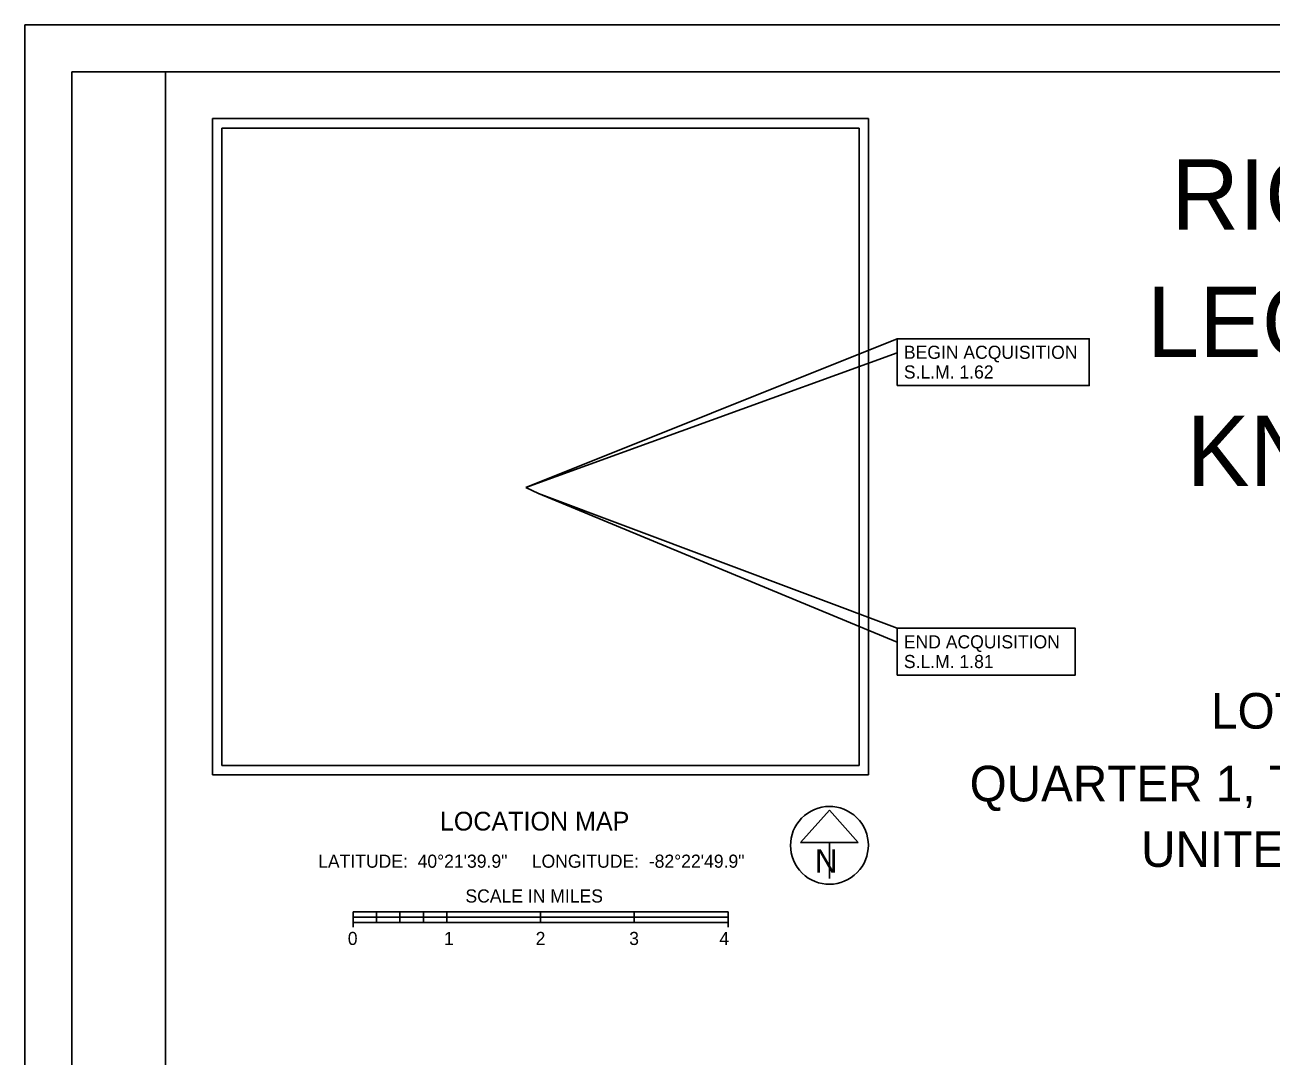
# Model space of a CAD drawing. Extents: x 0 to 104, y 0 to 37.
# Drawn here: x 0 to 13.29, y 11 to 22 of the extents above; entities that cross this region are included whole.
import ezdxf

# ---------------------------------------------------------------- set-up
doc = ezdxf.new("R2010")
doc.units = 0
for name, color, linetype in [('SC_Scratch3', 7, 'Continuous'), ('SH_Cut_Line', 7, 'Continuous'), ('SH_Data', 7, 'Continuous'), ('SH_Named_Boundary', 7, 'Continuous')]:
    doc.layers.add(name, color=color, linetype=linetype)

msp = doc.modelspace()

# ---------------------------------------------------------------- linework, layer by layer
at = {"layer": 'SC_Scratch3'}
msp.add_lwpolyline([(0, 0), (34, 0), (34, 22), (0, 22)], close=True, dxfattribs=at)
at = {"layer": 'SH_Data'}
for p, q in [((2, 21), (9, 21)), ((2, 21), (2, 14)), ((2.1, 20.9), (2.1, 14.1)), ((2.1, 20.9), (8.9, 20.9)), ((8.9, 20.9), (8.9, 14.1)), ((9, 21), (9, 14)), ((5.343, 17.067), (5.477, 17.003)), ((2.1, 14.1), (8.9, 14.1)), ((2, 14), (9, 14)), ((8.582, 13.622), (8.274, 13.28)), ((8.889, 13.28), (8.582, 13.622)), ((8.274, 13.28), (8.889, 13.28)), ((8.582, 13.28), (8.582, 12.894)), ((8.582, 13.248), (8.582, 13.248)), ((8.582, 13.248), (8.582, 13.248)), ((3.5, 12.538), (3.5, 12.375)), ((3.5, 12.538), (7.5, 12.538)), ((3.75, 12.425), (3.75, 12.538)), ((4, 12.425), (4, 12.538)), ((4.25, 12.538), (4.25, 12.425)), ((4.5, 12.425), (4.5, 12.538)), ((5.5, 12.538), (5.5, 12.425)), ((6.5, 12.425), (6.5, 12.538)), ((7.5, 12.375), (7.5, 12.538)), ((3.5, 12.481), (3.75, 12.481)), ((3.5, 12.425), (7.5, 12.425)), ((3.75, 12.481), (4, 12.481)), ((4.25, 12.481), (4, 12.481)), ((4.5, 12.481), (4.25, 12.481)), ((5.5, 12.481), (4.5, 12.481)), ((6.5, 12.481), (5.5, 12.481)), ((7.5, 12.481), (6.5, 12.481))]:
    msp.add_line(p, q, dxfattribs=at)
for points in [[(5.343, 17.067), (9.306, 18.503), (9.306, 18.653)], [(9.306, 18.153), (11.353, 18.153), (11.353, 18.653), (9.306, 18.653)], [(5.477, 17.003), (9.306, 15.414), (9.306, 15.564)], [(9.306, 15.064), (11.204, 15.064), (11.204, 15.564), (9.306, 15.564)], [(3.5, 12.538), (3.5, 12.481), (3.75, 12.481), (3.75, 12.538)], [(4, 12.538), (4, 12.481), (4.25, 12.481), (4.25, 12.538)], [(4.5, 12.538), (4.5, 12.481), (5.5, 12.481), (5.5, 12.538)], [(7.5, 12.538), (6.5, 12.538), (6.5, 12.481), (7.5, 12.481)], [(3.75, 12.425), (4, 12.425), (4, 12.481), (3.75, 12.481)], [(4.25, 12.425), (4.5, 12.425), (4.5, 12.481), (4.25, 12.481)], [(5.5, 12.425), (6.5, 12.425), (6.5, 12.481), (5.5, 12.481)]]:
    msp.add_lwpolyline(points, close=True, dxfattribs=at)
msp.add_arc((8.582, 13.248), 0.415, 129.7798, 129.7633, dxfattribs=at)
at = {"layer": 'SH_Named_Boundary'}
for points in [[(0.5, 21.5), (1.5, 21.5), (1.5, 0.5), (0.5, 0.5)], [(1.5, 21.5), (33.5, 21.5), (33.5, 0.5), (1.5, 0.5)]]:
    msp.add_lwpolyline(points, close=True, dxfattribs=at)

# ---------------------------------------------------------------- texts
at = {"layer": 'SH_Cut_Line'}
for s, height, p in [('RIGHT OF WAY', 0.75, (12.227, 19.816)), ('LEGEND SHEET', 0.75, (11.968, 18.457)), ('KNO-229-14.80', 0.75, (12.394, 17.082)), ('LOT 11 AND MILL RUN LOT ', 0.38, (12.653, 14.493))]:
    msp.add_text(s, height=height, dxfattribs=at).set_placement(p)
at = {"layer": 'SH_Data'}
for s, height, p in [('BEGIN ACQUISITION', 0.14, (9.376, 18.438)), ('S.L.M. 1.62', 0.14, (9.376, 18.228)), ('END ACQUISITION', 0.14, (9.376, 15.349)), ('S.L.M. 1.81', 0.14, (9.376, 15.139)), ('QUARTER 1, TOWNSHIP 6 NORTH, RANGE 12 WEST', 0.38, (10.078, 13.717)), ('LOCATION MAP', 0.2, (4.427, 13.406)), ('UNITED STATES MILITARY LANDS', 0.38, (11.907, 13.018)), ('N', 0.25, (8.426, 12.957)), ('LATITUDE:  40°21\'39.9"     LONGITUDE:  -82°22\'49.9"', 0.14, (3.128, 13.009)), ('SCALE IN MILES', 0.14, (4.699, 12.638)), ('0', 0.14, (3.444, 12.185)), ('1', 0.14, (4.471, 12.185)), ('2', 0.14, (5.448, 12.185)), ('3', 0.14, (6.446, 12.185)), ('4', 0.14, (7.408, 12.185))]:
    msp.add_text(s, height=height, dxfattribs=at).set_placement(p)

doc.saveas('drawing.dxf')
